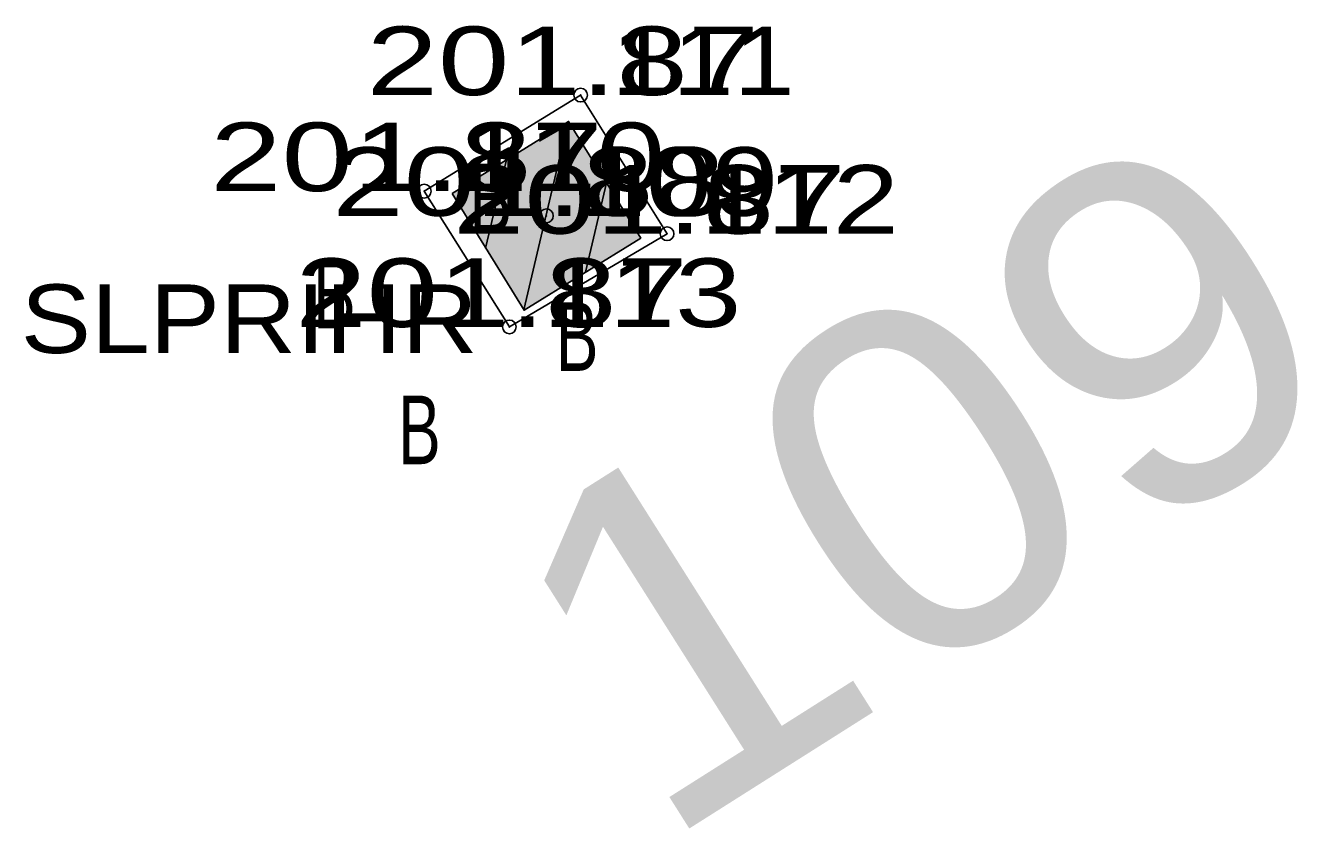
# Model space of a CAD drawing. Extents: x -466020 to -463400, y -1095586 to -1094005.
# Drawn here: x -465589.16 to -465579.87, y -1095586.25 to -1095580.39 of the extents above; entities that cross this region are included whole.
import ezdxf
from ezdxf.enums import TextEntityAlignment as Align

# ---------------------------------------------------------------- set-up
doc = ezdxf.new("R2010")
doc.units = 0
doc.header["$LTSCALE"] = 0.2
doc.header["$PDMODE"] = 32
doc.header["$PDSIZE"] = 0.1
for name, color, linetype in [('1', 7, 'Continuous'), ('2', 7, 'Continuous'), ('3', 7, 'Continuous'), ('4', 7, 'Continuous')]:
    doc.layers.add(name, color=color, linetype=linetype)
doc.layers.add('11', color=7, linetype='Continuous', lineweight=25)
doc.layers.add('12', color=7, linetype='Continuous', lineweight=25)

msp = doc.modelspace()

# ---------------------------------------------------------------- hatches: boundary and pattern name
at = {"layer": '11'}
msp.add_hatch(color=256, dxfattribs=at).paths.add_polyline_path([(-465586.048, -1095581.618), (-465585.198, -1095581.092), (-465584.672, -1095581.942), (-465585.522, -1095582.468)])

# ---------------------------------------------------------------- linework, layer by layer
at = {"layer": '1'}
for p in [(-465585.11, -1095580.9), (-465586.25, -1095581.6), (-465585.36, -1095581.78), (-465584.48, -1095581.91), (-465585.63, -1095582.59)]:
    msp.add_point(p, dxfattribs=at)
at = {"layer": '11'}
for p, q in [((-465585.524, -1095582.466), (-465585.2, -1095581.093)), ((-465585.803, -1095582.015), (-465585.651, -1095581.372)), ((-465585.074, -1095582.191), (-465584.921, -1095581.54))]:
    msp.add_line(p, q, dxfattribs=at)
msp.add_lwpolyline([(-465586.048, -1095581.618), (-465585.198, -1095581.092), (-465584.672, -1095581.942), (-465585.522, -1095582.468)], close=True, dxfattribs=at)
msp.add_lwpolyline([(-465586.048, -1095581.618), (-465585.198, -1095581.092), (-465584.672, -1095581.942), (-465585.522, -1095582.468)], close=True, dxfattribs=at)
at = {"layer": '12'}
msp.add_lwpolyline([(-465586.25, -1095581.6), (-465585.11, -1095580.9), (-465584.48, -1095581.91), (-465585.63, -1095582.59)], close=True, dxfattribs=at)

# ---------------------------------------------------------------- texts
at = {"layer": '11', "width": 1.1}
msp.add_text('109', height=2.5, rotation=32.334, dxfattribs=at).set_placement((-465581.9626, -1095584.7544), align=Align.CENTER)
at = {"layer": '2'}
for s, width, p in [(' 111', 1.2, (-465585.11, -1095580.9)), (' 110', 1.35, (-465586.25, -1095581.6)), (' 109', 1.3, (-465585.36, -1095581.78)), (' 112', 1.3, (-465584.48, -1095581.91)), (' 113', 1.3, (-465585.63, -1095582.59))]:
    msp.add_text(s, height=0.5, dxfattribs=dict(at, width=width)).set_placement(p)
at = {"layer": '3', "width": 1.4}
for s, p in [('201.87 ', (-465585.1095, -1095580.9)), ('201.87 ', (-465586.2495, -1095581.6)), ('201.88 ', (-465585.3595, -1095581.78)), ('201.87 ', (-465584.4795, -1095581.91)), ('201.87 ', (-465585.6295, -1095582.59))]:
    msp.add_text(s, height=0.5, dxfattribs=at).set_placement(p, align=Align.CENTER)
at = {"layer": '4'}
for s, width, p in [('B', 0.7, (-465585.61, -1095581.9)), ('B', 0.7, (-465586.75, -1095582.6)), ('SLPRIHR', 1.15, (-465585.86, -1095582.78)), ('B', 0.7, (-465584.98, -1095582.91)), ('B', 0.7, (-465586.13, -1095583.59))]:
    msp.add_text(s, height=0.5, dxfattribs=dict(at, width=width)).set_placement(p, align=Align.RIGHT)

doc.saveas('drawing.dxf')
